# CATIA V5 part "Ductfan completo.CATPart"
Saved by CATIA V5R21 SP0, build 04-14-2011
Part number: Ductfan
Material "Grey Blue": density 7860 kg/m3, Young's modulus 2e+11 Pa, Poisson ratio 0.266
Bounding box of the stored display mesh (mm): x -344.98 to 394.667, y -40 to 360, z -344.802 to 344.802
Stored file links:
  C:\Users\rodri\OneDrive\Área de Trabalho\FACULDADE\3°semestre\Sistemas Aeroespaciais\Projeto de avião 2019-02\CAD\Ductfan completo.CATPart
  C:\Users\andre\AppData\Local\Temp\Rar$DIa18808.12376\NACA 2412 3D Aerofoil.CATPart
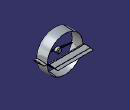
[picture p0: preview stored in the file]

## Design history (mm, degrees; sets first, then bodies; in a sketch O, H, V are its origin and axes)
Body1 (main body)
  Sketch1 on yz-plane, origin (0, 0, 0), H (0, 1, 0), V (0, 0, 1)
    point P1 (-40, -336.52)
    point P2 (160, -336.52)
    unspec C1
    unspec C2
    axis line L1 (0, -34.7251) -> (0, -104.5277)
    distance P1 P2 = 200
    distance C1 C2 = 23.9924
    distance P1 L1 = 40
    distance C1 H = 320.675
    distance P2 H = 336.52
    vertical: L1 V
    coincidence: L1 V
  Shaft1: profile Sketch1, axis Sketch1.H, angle 360
  Sketch2 on zx-plane, origin (0, 0, 0), H (-1, 0, 0), V (0, 0, 1)
    circle A1 centre (0, 0) radius 45.8
    radius A1 = 45.8
  Pad1: profile Sketch2, direction (0, 1, 0), length 60
  Fillet1: radius 10, on edge [face of Pad1 from Sketch2.A1 | end face of Pad1]
  Sketch3 on start face of Pad1, origin (0, 0, 0), H (1, 0, 0), V (0, 0, 1)
    circle A1 centre (0, 0) radius 10
    point P1 (10, 0)
    radius A1 = 10
    coincidence: A1 P1, P1 H
  Pocket1: profile Sketch3, direction (0, 1, 0), length 10
  Sketch4 on start face of Pad1, origin (0, 0, 0), H (1, 0, 0), V (0, 0, 1)
    ellipse A1 centre (0, 0) semi-axes 306.75, 10 rotation 172.047
    "Radius" A1 = 306.75
    distance A1 O = 10
  Pad2: profile Sketch4, direction (0, -1, 0), length 10
  Plane1: type Offset, RefPlane yz-plane, Offset 344.667, reversed
  Sketch5 on Plane1, origin (-344.667, 0, 0), H (0, 1, 0), V (0, 0, 1)
    point P1 (-40, -2.4533)
    point P2 (160, -2.4533)
    unspec C1
    unspec C2
    circle A1 centre (0, 0) radius 5
    point P3 (0, 0)
    circle A2 centre (60.03, -0.0038) radius 5
    point P4 (60.03, -0.0038)
    distance P1 P2 = 200
    distance P1 V = 40
    radius A1 = 5
    distance C1 C2 = 23.9924
    distance P3 C1 = 11.996
    distance P3 P1 = 40.0752
    radius A2 = 5
    distance P4 P2 = 100
    distance P4 C1 = 11.996
    distance P3 H = 0
    coincidence: P3 V
  Pad3: profile Sketch5, direction (-1, 0, 0), length 50
  Sketch6 on yz-plane, origin (0, 0, 0), H (0, 1, 0), V (0, 0, 1)
    point P1 (160, -0.1822)
    unspec C1
    unspec C2
    point P3 (26.5548, 0)
    point P4 (180, 2)
    circle A1 centre (180, 2) radius 5
    point P5 (184.5826, 0)
    line L1 (190, 11) -> (196, 11)
    line L2 (196, 11) -> (196, -6)
    line L3 (196, -6) -> (190, -6)
    line L4 (190, -6) -> (190, 11)
    point P10 (210, 3)
    circle A2 centre (210, 3) radius 7.5
    point P11 (235, 4)
    circle A3 centre (235, 4) radius 7.5
    point P12 (260, 4)
    circle A4 centre (260, 4) radius 7.5
    point P13 (285, 3)
    circle A5 centre (285, 3) radius 5
    line L5 (300, 8) -> (304, 8)
    line L6 (304, 8) -> (304, -2)
    line L7 (304, -2) -> (300, -2)
    line L8 (300, -2) -> (300, 8)
    radius A1 = 5
    distance H P4 = 2
    distance V P4 = 180
    distance L4 L2 = 6
    distance L1 L3 = 17
    distance L3 H = 6
    distance L4 V = 190
    radius A2 = 7.5
    distance P10 H = 3
    distance P10 V = 210
    radius A3 = 7.5
    distance P11 H = 4
    radius A4 = 7.5
    distance P11 V = 235
    distance P12 H = 4
    distance P12 V = 260
    radius A5 = 5
    distance P13 H = 3
    distance P13 V = 285
    distance L5 L7 = 10
    distance L8 L6 = 4
    distance L8 V = 300
    distance L7 H = 2
    distance P1 V = 160
    coincidence: A1 P5, P5 H
    horizontal: L1 H, L3 H, L5 H, L7 H
    vertical: L2 V, L4 V, L6 V, L8 V
  Pad4: profile Sketch6, direction (1, 0, 0), length 336.52, mirrored extent
  Sketch7 on end face of Pad4, origin (336.52, 0, 0), H (0, 1, 0), V (0, 0, 1)
    point P2 (360, 0)
    unspec C1
    unspec C2
    distance P2 V = 360
  Pad5: profile Sketch7, direction (1, 0, 0), length 5
  Fillet2: radius 2, on end face of Pad5
  Symmetry1: ToTransfor Fillet2, Reference yz-plane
